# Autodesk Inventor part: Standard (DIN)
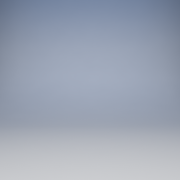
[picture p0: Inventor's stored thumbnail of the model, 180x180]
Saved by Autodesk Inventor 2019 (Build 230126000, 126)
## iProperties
Created: 2018-02
Part Number: Standard (DIN)
Material: Všeobecné
Document SubType Name: Modeling
Density: 1 g/cm^3
Appearance: Výchozí
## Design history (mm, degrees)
